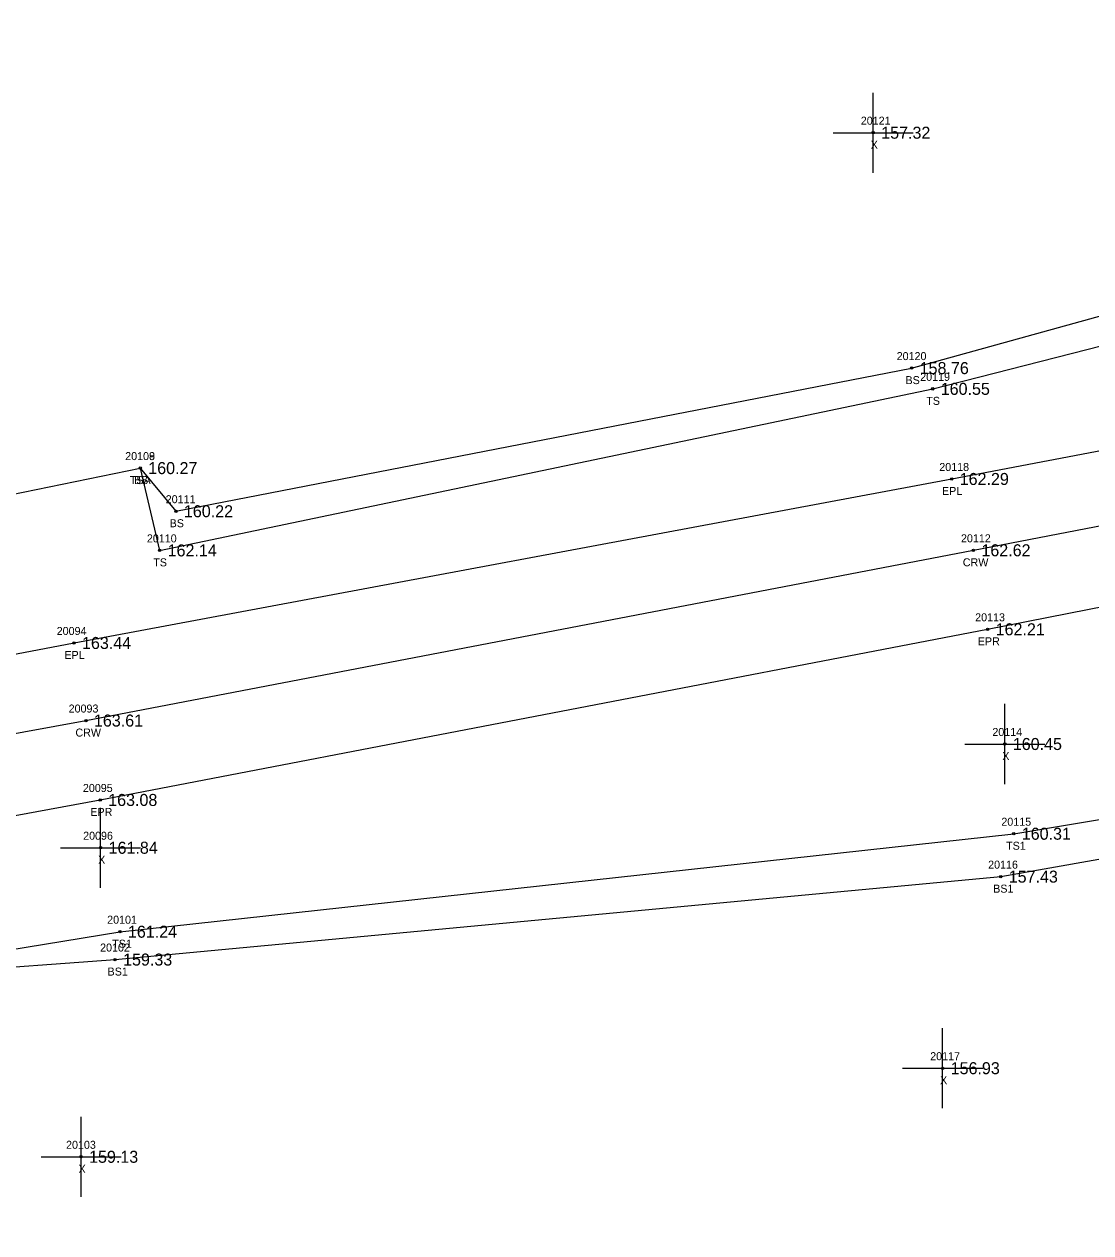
# Model space of a CAD drawing. Extents: x 2381545 to 2382928, y 1029933 to 1030589.
# Drawn here: x 2381889.7 to 2382022.9, y 1030248.4 to 1030399.4 of the extents above; entities that cross this region are included whole.
import ezdxf

# ---------------------------------------------------------------- set-up
doc = ezdxf.new("R2010")
doc.units = 0
for name, color, linetype in [('RD_DTM_BkLn1', 7, 'Continuous'), ('RD_DTM_BkLn2', 7, 'Continuous'), ('RD_DTM_BkLn_txCode', 7, 'Continuous'), ('RD_EX_Misc', 7, 'Continuous'), ('RD_EX_Misc_txCode', 7, 'Continuous'), ('RD_EX_Road', 7, 'Continuous'), ('RD_EX_Road_txCode', 7, 'Continuous'), ('RD_EX_TX_Misc_ELEV', 7, 'Continuous'), ('RD_EX_TX_Road_ELEV', 7, 'Continuous'), ('RD_HC_Survey_ELEV', 7, 'Continuous'), ('RD_HC_Survey_txCode', 7, 'Continuous'), ('RD_SMD_Locator', 7, 'Continuous')]:
    doc.layers.add(name, color=color, linetype=linetype)

msp = doc.modelspace()

# ---------------------------------------------------------------- linework, layer by layer
at = {"layer": 'RD_DTM_BkLn1'}
msp.add_lwpolyline([(2381547.18, 1030259.1), (2381595.71, 1030262.71), (2381646.12, 1030268.56), (2381695.78, 1030276.09), (2381799.52, 1030294.49), (2381897.44, 1030312.39), (2382008.24, 1030333.66), (2382118.08, 1030354.86), (2382202.13, 1030371.04)], dxfattribs=at)
at = {"layer": 'RD_DTM_BkLn2'}
for points in [[(2381793.09, 1030313.94), (2381875.92, 1030331.56), (2381878.21, 1030338.59), (2381904.22, 1030343.93), (2381908.67, 1030338.54), (2382000.53, 1030356.42), (2382114.53, 1030387.99), (2382160.73, 1030399.39)], [(2381904.22, 1030343.93), (2381906.64, 1030333.65), (2382003.16, 1030353.83), (2382114.61, 1030382.31), (2382198.59, 1030390.09), (2382200, 1030380.28)], [(2381785.89, 1030275.89), (2381871.01, 1030288.93), (2381880.52, 1030282.55), (2381901.68, 1030286.01), (2382013.28, 1030298.25), (2382122.09, 1030316.46), (2382195.01, 1030325.62), (2382206, 1030331.71), (2382212.25, 1030344.58), (2382207.28, 1030357.44), (2382204.69, 1030361.31)], [(2381786.8, 1030272.08), (2381870.97, 1030285.18), (2381880.6, 1030281.02), (2381901.08, 1030282.53), (2382011.65, 1030292.89), (2382122.26, 1030312.46), (2382194.74, 1030319.65), (2382207.56, 1030328.92), (2382216.83, 1030343.34)]]:
    msp.add_lwpolyline(points, dxfattribs=at)
at = {"layer": 'RD_EX_Misc'}
for p, q in [((2381995.73, 1030380.83), (2381995.73, 1030390.83)), ((2381990.73, 1030385.83), (2382000.73, 1030385.83)), ((2382012.16, 1030304.46), (2382012.16, 1030314.46)), ((2382007.16, 1030309.46), (2382017.16, 1030309.46)), ((2381899.27, 1030291.5), (2381899.27, 1030301.5)), ((2381894.27, 1030296.5), (2381904.27, 1030296.5)), ((2382004.4, 1030263.96), (2382004.4, 1030273.96)), ((2381999.4, 1030268.96), (2382009.4, 1030268.96)), ((2381896.83, 1030252.89), (2381896.83, 1030262.89)), ((2381891.83, 1030257.89), (2381901.83, 1030257.89))]:
    msp.add_line(p, q, dxfattribs=at)
at = {"layer": 'RD_EX_Road'}
for points in [[(2381547.21, 1030268.01), (2381595.28, 1030271.86), (2381645.28, 1030277.12), (2381675.41, 1030281.84), (2381694.68, 1030285.03), (2381797.68, 1030303.35), (2381895.95, 1030322.08), (2382005.53, 1030342.57), (2382116.42, 1030363.72), (2382200, 1030380.28), (2382202.13, 1030371.04)], [(2381547.49, 1030248.39), (2381596.55, 1030252.33), (2381646.64, 1030258.33), (2381698.19, 1030266.34), (2381800.73, 1030284.35), (2381899.22, 1030302.47), (2382010.02, 1030323.79), (2382119.81, 1030345.41), (2382204.69, 1030361.31), (2382202.13, 1030371.04)]]:
    msp.add_lwpolyline(points, dxfattribs=at)
at = {"layer": 'RD_SMD_Locator'}
for centre in [(2381995.73, 1030385.83), (2382000.53, 1030356.42), (2382003.16, 1030353.83), (2381904.22, 1030343.93), (2381904.22, 1030343.93), (2382005.53, 1030342.57), (2381908.67, 1030338.54), (2381906.64, 1030333.65), (2382008.24, 1030333.66), (2382010.02, 1030323.79), (2381895.95, 1030322.08), (2381897.44, 1030312.39), (2382012.16, 1030309.46), (2381899.22, 1030302.47), (2382013.28, 1030298.25), (2381899.27, 1030296.5), (2382011.65, 1030292.89), (2381901.68, 1030286.01), (2381901.08, 1030282.53), (2382004.4, 1030268.96), (2381896.83, 1030257.89)]:
    msp.add_circle(centre, 0.15, dxfattribs=at)

# ---------------------------------------------------------------- texts
at = {"layer": 'RD_DTM_BkLn_txCode'}
for s, p in [('20120', (2381998.66, 1030357.42)), ('BS', (2381999.76, 1030354.42)), ('20119', (2382001.6, 1030354.83)), ('TS', (2382002.36, 1030351.83)), ('20108', (2381902.34, 1030344.93)), ('20109', (2381902.34, 1030344.93)), ('TSA', (2381902.93, 1030341.93)), ('BS', (2381903.44, 1030341.93)), ('20111', (2381907.4, 1030339.54)), ('BS', (2381907.89, 1030336.54)), ('20110', (2381905.05, 1030334.65)), ('TS', (2381905.85, 1030331.65)), ('20115', (2382011.73, 1030299.25)), ('TS1', (2382012.32, 1030296.25)), ('20116', (2382010.08, 1030293.89)), ('BS1', (2382010.71, 1030290.89)), ('20101', (2381900.09, 1030287.01)), ('20102', (2381899.21, 1030283.53)), ('TS1', (2381900.72, 1030284.01)), ('BS1', (2381900.14, 1030280.53))]:
    msp.add_text(s, height=1, dxfattribs=at).set_placement(p)
at = {"layer": 'RD_EX_Misc_txCode'}
for s, p in [('20121', (2381994.18, 1030386.83)), ('X', (2381995.42, 1030383.83)), ('20114', (2382010.61, 1030310.46)), ('X', (2382011.85, 1030307.46)), ('20096', (2381897.09, 1030297.5)), ('X', (2381898.96, 1030294.5)), ('20117', (2382002.85, 1030269.96)), ('X', (2382004.08, 1030266.96)), ('20103', (2381894.96, 1030258.89)), ('X', (2381896.51, 1030255.89))]:
    msp.add_text(s, height=1, dxfattribs=at).set_placement(p)
at = {"layer": 'RD_EX_Road_txCode'}
for s, p in [('20118', (2382003.98, 1030343.57)), ('EPL', (2382004.32, 1030340.57)), ('20113', (2382008.46, 1030324.79)), ('20094', (2381893.79, 1030323.08)), ('EPR', (2382008.79, 1030321.79)), ('EPL', (2381894.75, 1030320.08)), ('20095', (2381897.06, 1030303.47)), ('EPR', (2381897.99, 1030300.47))]:
    msp.add_text(s, height=1, dxfattribs=at).set_placement(p)
at = {"layer": 'RD_EX_TX_Misc_ELEV'}
for s, p in [('157.32', (2381996.73, 1030385.08)), ('158.76', (2382001.53, 1030355.67)), ('160.55', (2382004.16, 1030353.08)), ('160.27', (2381905.22, 1030343.18)), ('160.27', (2381905.22, 1030343.18)), ('160.22', (2381909.67, 1030337.79)), ('162.14', (2381907.64, 1030332.9)), ('160.45', (2382013.16, 1030308.71)), ('160.31', (2382014.28, 1030297.5)), ('161.84', (2381900.27, 1030295.75)), ('157.43', (2382012.65, 1030292.14)), ('161.24', (2381902.68, 1030285.26)), ('159.33', (2381902.08, 1030281.78)), ('156.93', (2382005.4, 1030268.21)), ('159.13', (2381897.83, 1030257.14))]:
    msp.add_text(s, height=1.5, dxfattribs=at).set_placement(p)
at = {"layer": 'RD_EX_TX_Road_ELEV'}
for s, p in [('162.29', (2382006.53, 1030341.82)), ('162.21', (2382011.02, 1030323.04)), ('163.44', (2381896.95, 1030321.33)), ('163.08', (2381900.22, 1030301.72))]:
    msp.add_text(s, height=1.5, dxfattribs=at).set_placement(p)
at = {"layer": 'RD_HC_Survey_ELEV'}
for s, p in [('162.62', (2382009.24, 1030332.91)), ('163.61', (2381898.44, 1030311.64))]:
    msp.add_text(s, height=1.5, dxfattribs=at).set_placement(p)
at = {"layer": 'RD_HC_Survey_txCode'}
for s, p in [('20112', (2382006.69, 1030334.66)), ('CRW', (2382006.92, 1030331.66)), ('20093', (2381895.28, 1030313.39)), ('CRW', (2381896.13, 1030310.39))]:
    msp.add_text(s, height=1, dxfattribs=at).set_placement(p)

doc.saveas('drawing.dxf')
